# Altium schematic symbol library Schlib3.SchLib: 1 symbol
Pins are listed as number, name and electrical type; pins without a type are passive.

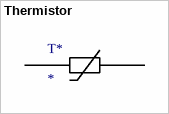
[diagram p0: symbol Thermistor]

## Thermistor
designator T*
footprint PCBComponent_1
pins: 1, 2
